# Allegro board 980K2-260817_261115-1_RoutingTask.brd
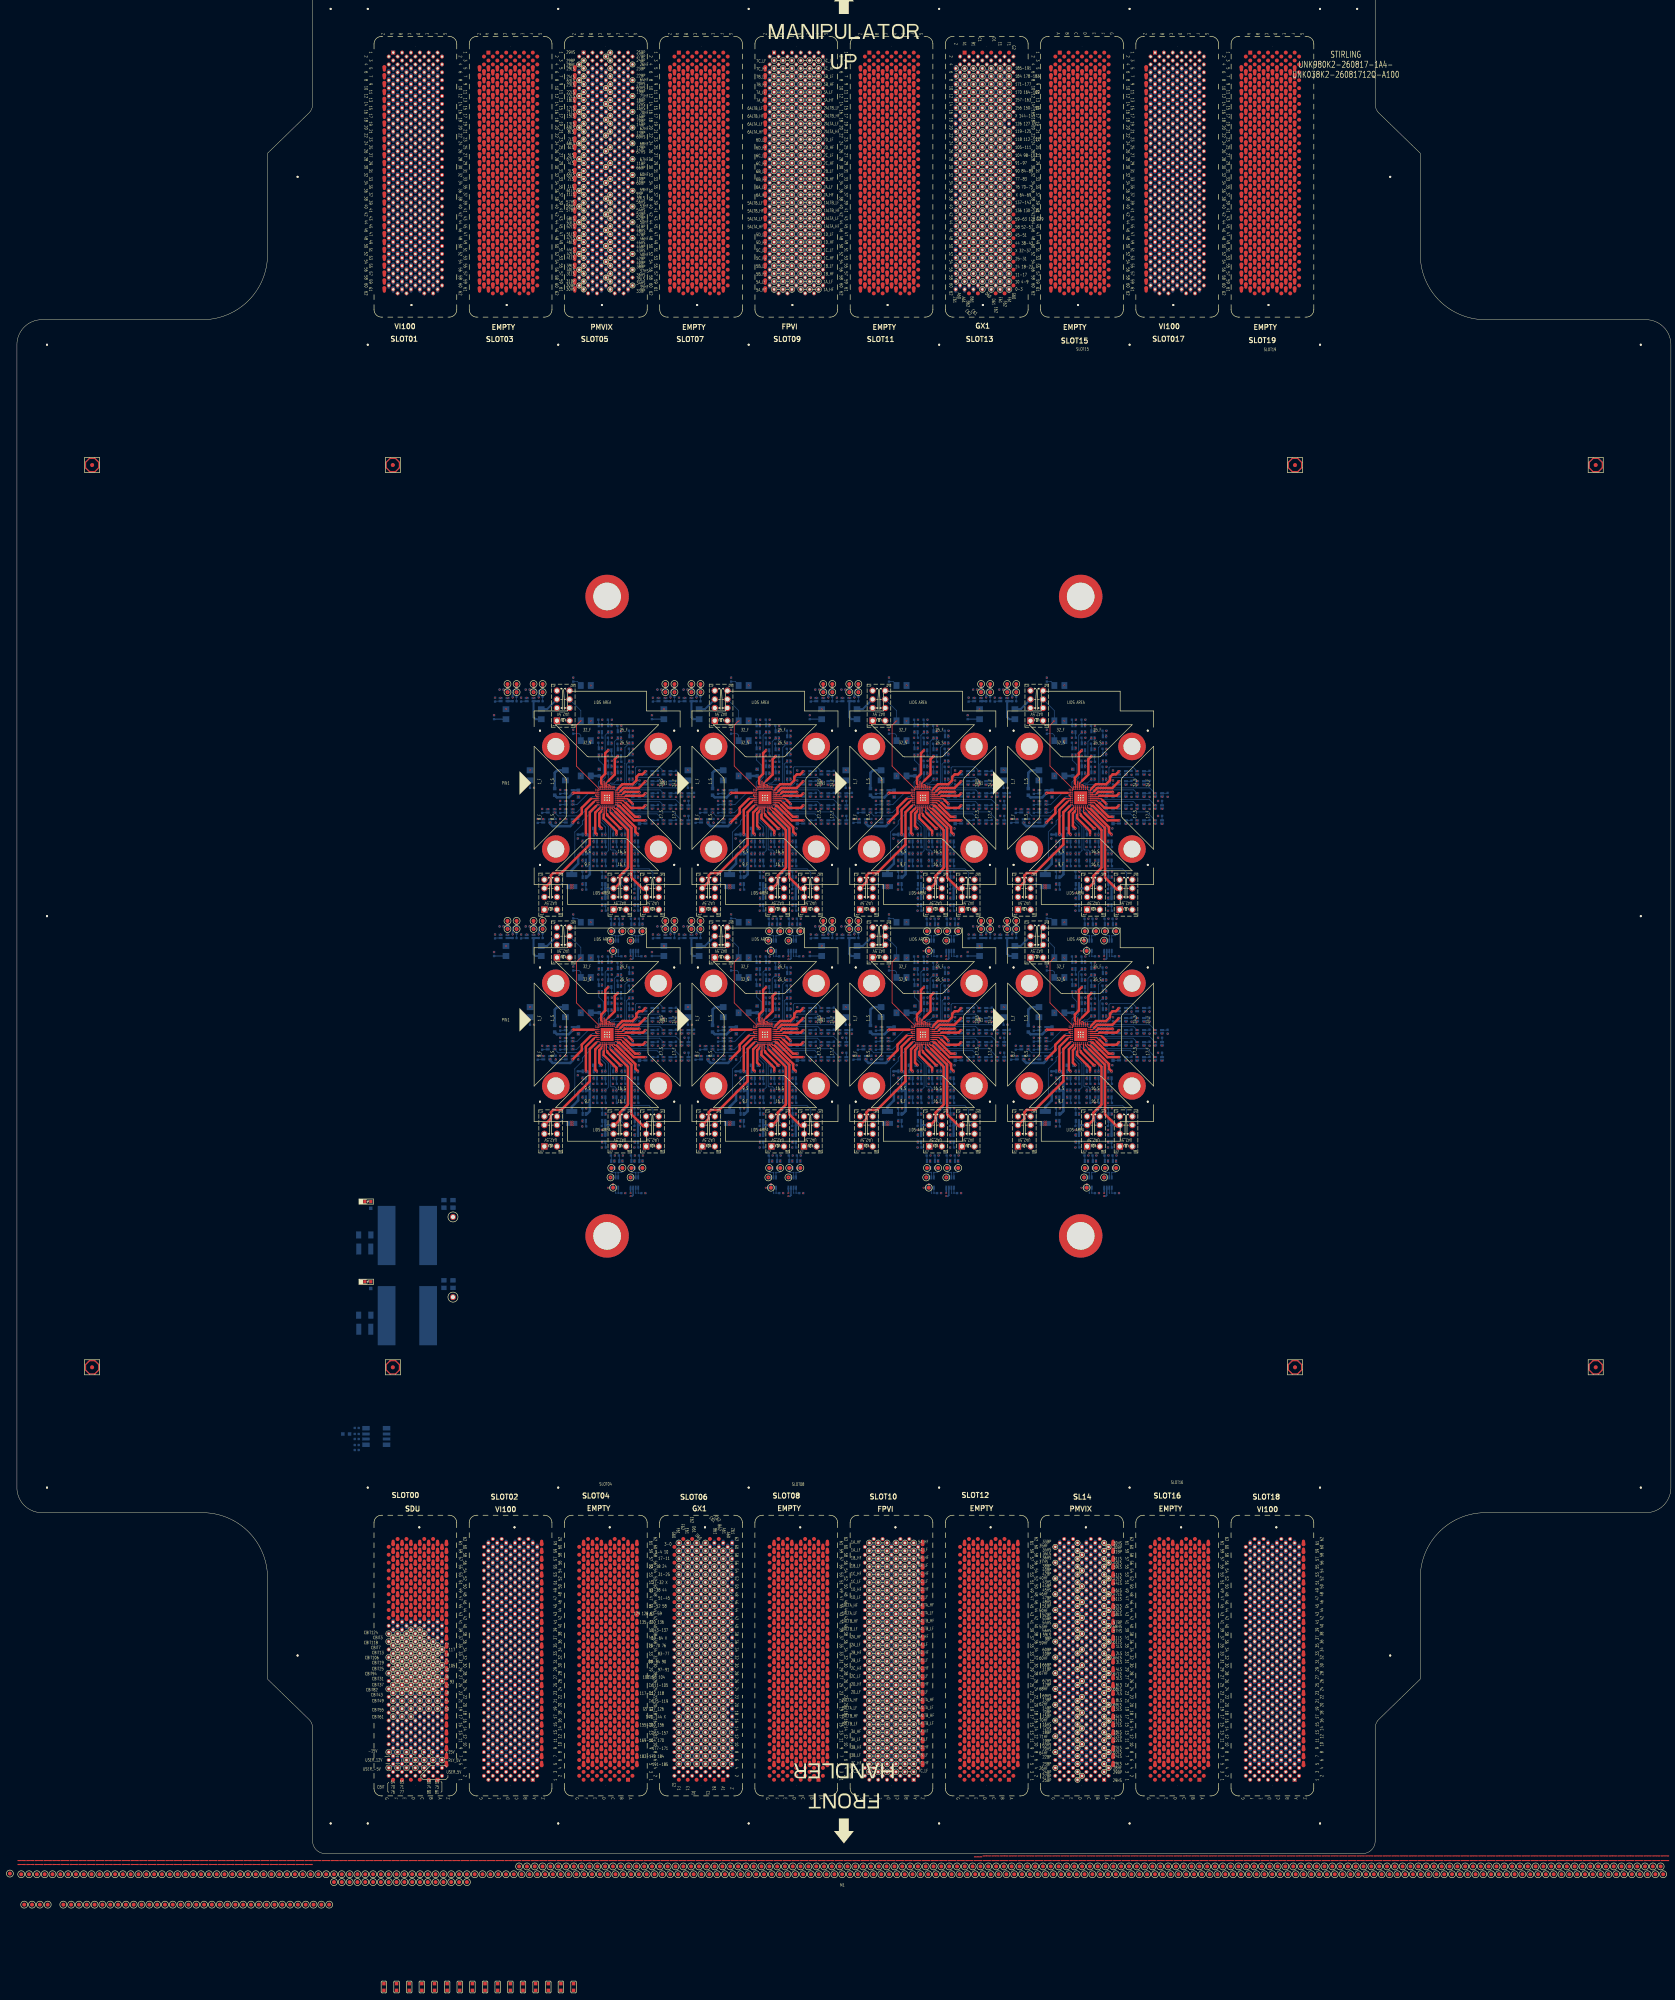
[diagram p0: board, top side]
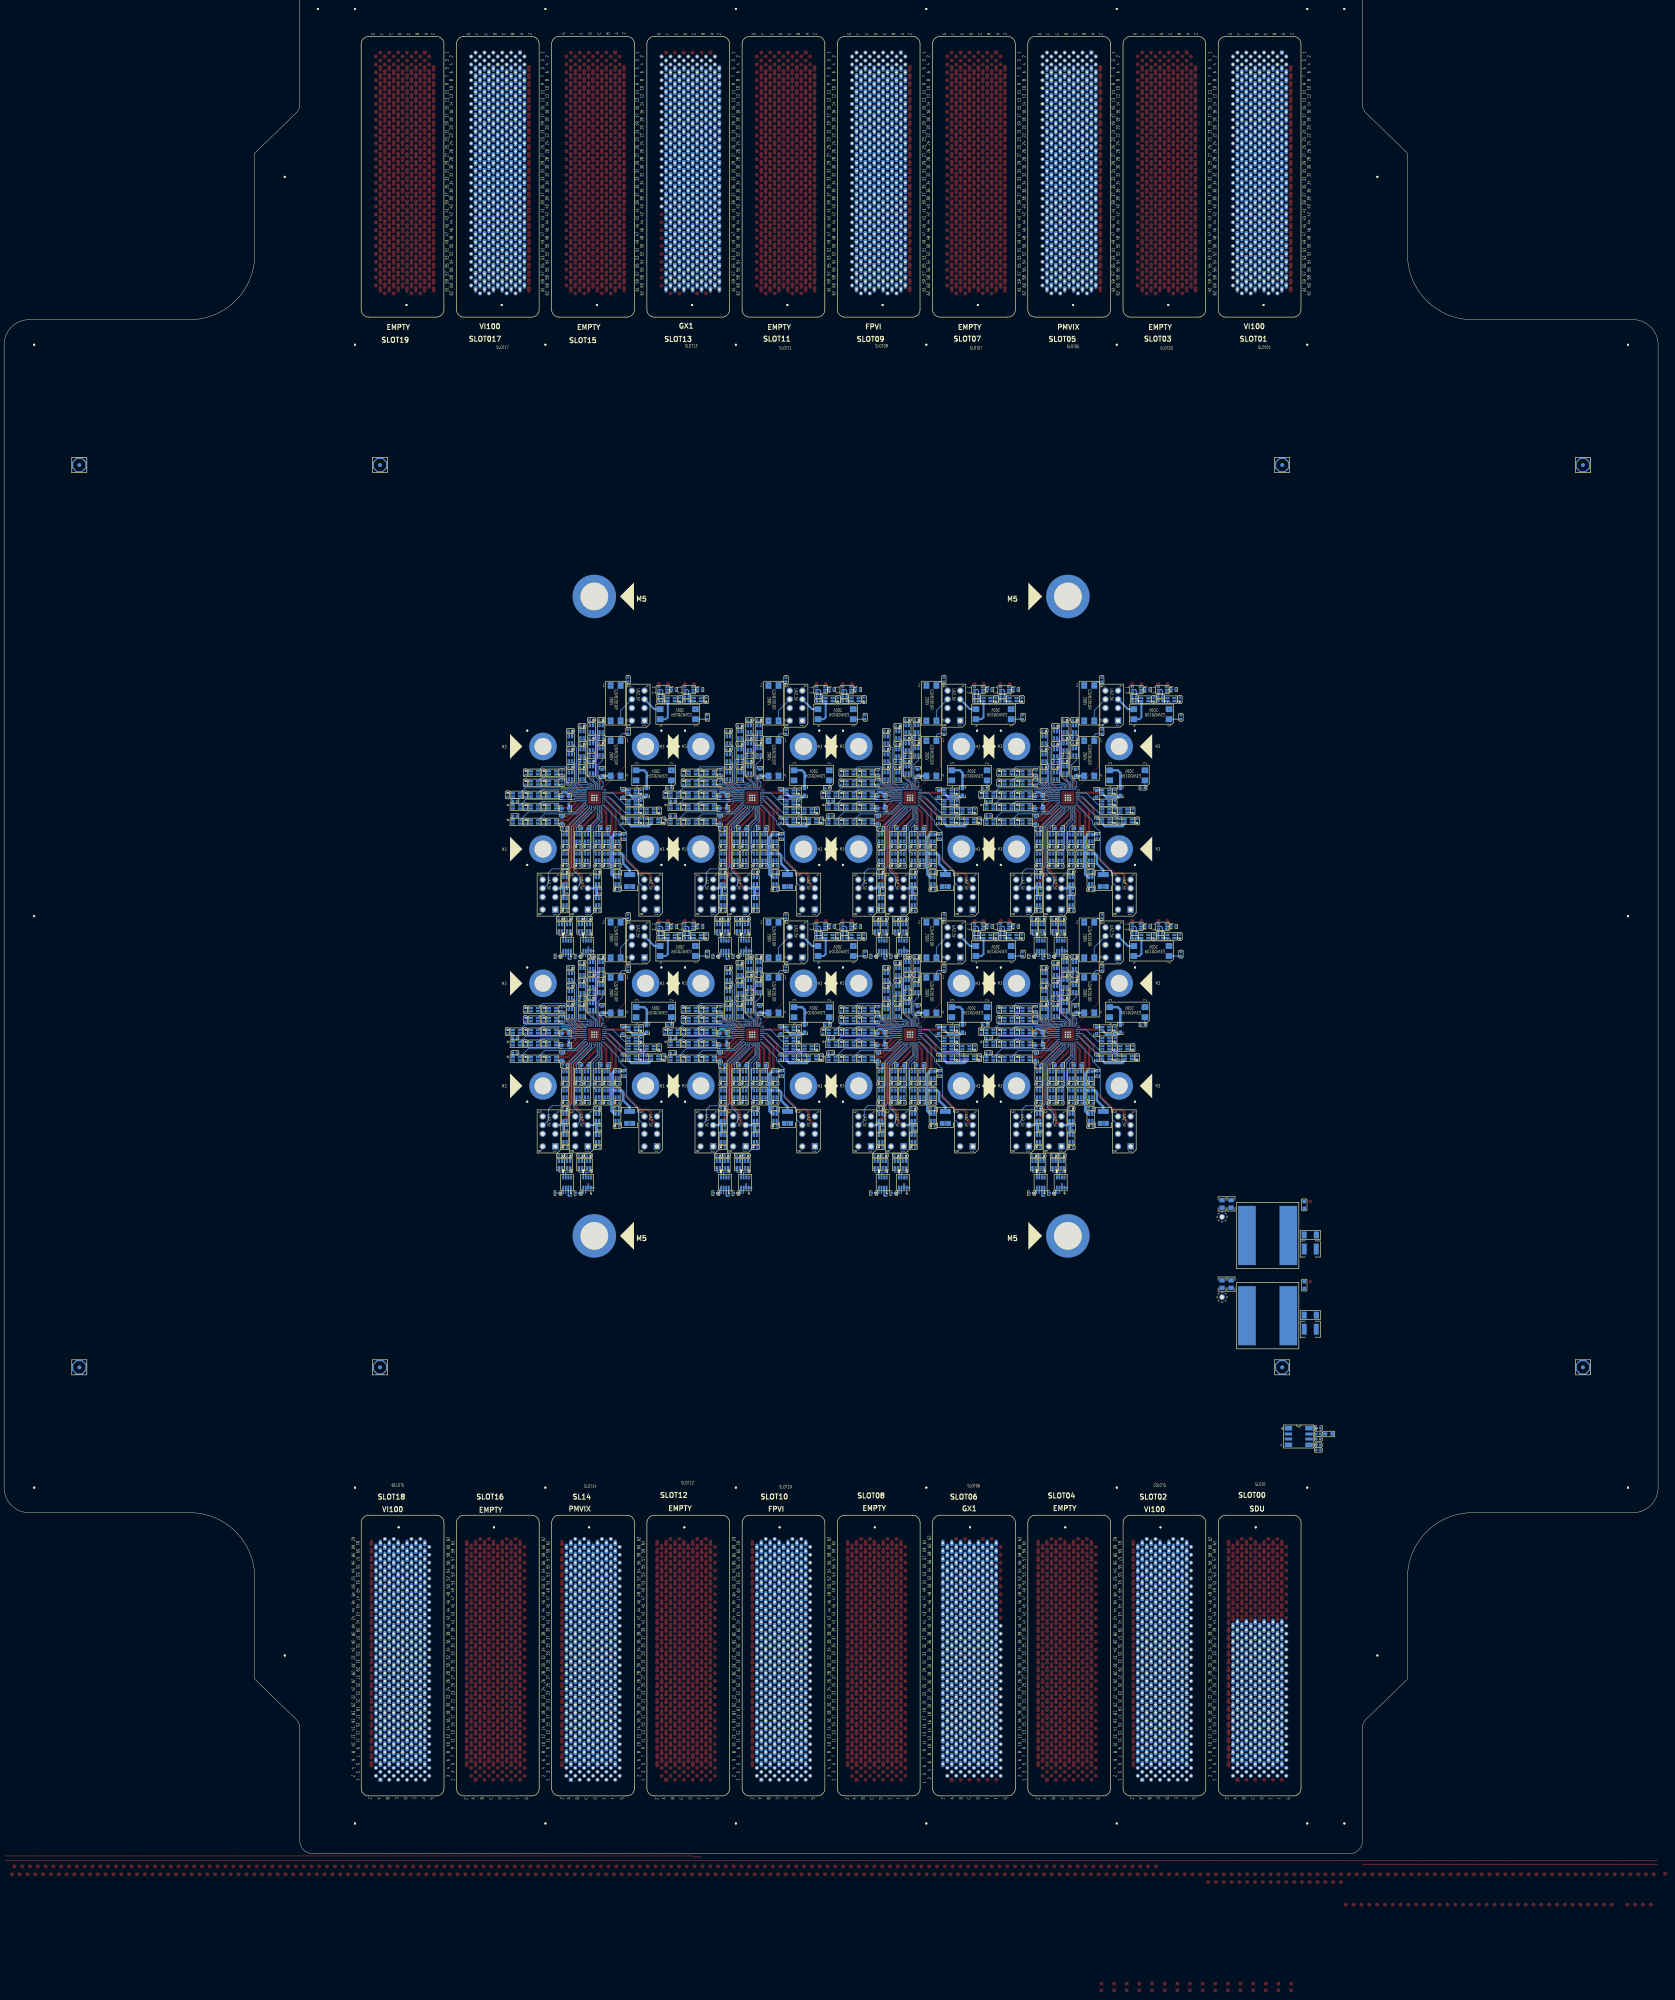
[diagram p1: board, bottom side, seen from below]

Outline 419.1 x 474.98 mm; copper layers: TOP, L02_GND, L03_DP, L04_GND, L05_DP, L06_GND, L07_VI, L08_GND, L09_VI, L10_GND, L11_VI, L12_GND, L13_VI, L14_GND, L15_5V, L16_5V, L17_C-BIT, L18_C-BIT, L19_GND, L20_VI, L21_GND, L22_VI, L23_GND, L24_VI, L25_GND, L26_VI, L27_GND, L28_DP, L29_GND, L30_DP, L31_GND, BOTTOM. Coordinates in mm from the lower left corner of the outline.

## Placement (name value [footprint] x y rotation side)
BC9  0.1U-50-X-S4-TDK  [C0402]  86.11 107.82 180 bottom
BR5  1K-1-S4  [R0402]  86.11 106.3 0 bottom
BR6  1K-1-S4  [R0402]  86.11 103.5 0 bottom
BR7  0-5-S6  [R0603]  83.44 106.3 180 bottom
BR8  0-5-S4  [R0402]  86.11 105.03 180 bottom
BR9  0-5-S4  [R0402]  86.11 102.24 180 bottom
BU1  AT24C512C-SSHM-T-SOIC8  [SO8_206X127MM]  91.06 105.66 180 bottom
C48  0.01U-100-X7R-S6-MU  [C0603]  147.57 273.87 90 bottom
C49  0.01U-100-X7R-S6-MU  [C0603]  136.27 268.99 270 bottom
C50  0.01U-100-X7R-S6-MU  [C0603]  142.28 268.54 270 bottom
C53  1U-16-X5R-S4-YA  [C0402]  142.24 261.62 270 bottom
C54  2.2U-16-X-S4-MU  [C0402]  136.53 261.62 270 bottom
C58  1U-16-X5R-S4-YA  [C0402]  142.11 257.68 270 bottom
C59  4.7U-100-X-SB-MU  [C1210]  140.59 246.51 270 bottom
C60  0.01U-100-X7R-S6-MU  [C0603]  147.01 259.72 0 bottom
C61  0.01U-100-X7R-S6-MU  [C0603]  156.88 264.78 180 bottom
C62  2.2U-16-X-S4-MU  [C0402]  157.07 259.72 0 bottom
C63  0.01U-100-X7R-S6-MU  [C0603]  157.73 261.82 90 bottom
C64  0.01U-100-X7R-S6-MU  [C0603]  156.88 267.82 180 bottom
C65  0.1U-25-X7R-S4-MU  [C0402]  157.73 271.37 90 bottom
C66  0.1U-25-X7R-S4-MU  [C0402]  152.65 276.61 180 bottom
C67  0.1U-25-X7R-S4-MU  [C0402]  150.24 278.13 180 bottom
C68  0.1U-25-X7R-S4-MU  [C0402]  147.83 282.7 180 bottom
C69  0.01U-100-X7R-S6-MU  [C0603]  151.96 259.72 0 bottom
C70  0.1U-25-X7R-S4-MU  [C0402]  122.8 294.89 180 bottom
C71  0.1U-25-X7R-S4-MU  [C0402]  129.42 294.89 180 bottom
C72  0.1U-25-X7R-S4-MU  [C0402]  158.75 227.33 0 bottom
C73  0.1U-25-X7R-S4-MU  [C0402]  153.67 227.33 0 bottom
C74  0.1U-25-X7R-S4-MU  [C0402]  157.73 273.91 90 bottom
CT1  47U-16-X5R-SB-MU  [C1210]  88.14 153.16 180 bottom
CT2  10U-16-X5R-S8-TY  [C0805]  108.2 164.59 90 bottom
CT3  22U-16-X-S8-MU  [C0805]  110.49 164.59 90 bottom
CT7  47U-16-X5R-SB-MU  [C1210]  88.14 132.84 180 bottom
CT8  10U-16-X5R-S8-TY  [C0805]  110.49 144.27 90 bottom
CT9  22U-16-X-S8-MU  [C0805]  108.2 144.27 90 bottom
F1  C1F8-0.25A-SA  [FUSE_1206_H1P05MM]  88.14 156.72 0 bottom
F2  C1F8-0.25A-SA  [FUSE_1206_H1P05MM]  88.14 136.4 0 bottom
FD1  -  [FD_040_V2]  95.25 123.19 0 top
FD2  -  [FD_040_V2]  323.85 123.19 0 top
FD3  -  [FD_040_V2]  323.85 351.79 0 top
FD4  -  [FD_040_V2]  95.25 351.79 0 top
FD5  -  [FD_040_V2]  323.85 123.19 180 bottom
FD6  -  [FD_040_V2]  95.25 123.19 180 bottom
FD7  -  [FD_040_V2]  95.25 351.79 180 bottom
FD8  -  [FD_040_V2]  323.85 351.79 180 bottom
FD9  -  [FD_040_V2]  19.05 123.19 0 top
FD10  -  [FD_040_V2]  400.05 123.19 0 top
FD11  -  [FD_040_V2]  400.05 351.79 0 top
FD12  -  [FD_040_V2]  19.05 351.79 0 top
FD13  -  [FD_040_V2]  400.05 123.19 180 bottom
FD14  -  [FD_040_V2]  19.05 123.19 180 bottom
FD15  -  [FD_040_V2]  19.05 351.79 180 bottom
FD16  -  [FD_040_V2]  400.05 351.79 180 bottom
K1  UA2-5NJ-A-V3  [RL_NECUA2_5V_V3]  138.43 290.63 270 bottom
K2  G3VM-201DR  [RL_G3VM201DR_200V]  144.15 277.5 0 bottom
K3  G3VM-201DR  [RL_G3VM201DR_200V]  134.49 273.18 90 bottom
K4  G3VM-201DR  [RL_G3VM201DR_200V]  144.15 291.47 0 bottom
K5  G3VM-51UR-5V-VSON4  [RL_G3VM_4P_VSON4]  139.95 268.99 0 bottom
K6  G3VM-51UR-5V-VSON4  [RL_G3VM_4P_VSON4]  139.95 266.19 0 bottom
K7  G3VM-51UR-5V-VSON4  [RL_G3VM_4P_VSON4]  139.95 264.16 0 bottom
K8  G3VM-51UR-5V-VSON4  [RL_G3VM_4P_VSON4]  139.95 261.62 0 bottom
K9  G3VM-51UR-5V-VSON4  [RL_G3VM_4P_VSON4]  134.24 261.62 0 bottom
K10  G3VM-51UR-5V-VSON4  [RL_G3VM_4P_VSON4]  135.38 264.16 0 bottom
K11  G3VM-51UR-5V-VSON4  [RL_G3VM_4P_VSON4]  143.76 257.3 90 bottom
K12  G3VM-51UR-5V-VSON4  [RL_G3VM_4P_VSON4]  143.76 252.48 90 bottom
K13  G3VM-51UR-5V-VSON4  [RL_G3VM_4P_VSON4]  143.76 246.51 90 bottom
K14  G3VM-51UR-5V-VSON4  [RL_G3VM_4P_VSON4]  146.56 252.48 90 bottom
K15  UA2-5NJ-A-V3  [RL_NECUA2_5V_V3]  135.25 242.75 270 bottom
K16  G3VM-51UR-5V-VSON4  [RL_G3VM_4P_VSON4]  146.56 257.3 90 bottom
K17  G3VM-51UR-5V-VSON4  [RL_G3VM_4P_VSON4]  148.72 257.3 90 bottom
K18  G3VM-51UR-5V-VSON4  [RL_G3VM_4P_VSON4]  148.72 252.48 90 bottom
K19  G3VM-51UR-5V-VSON4  [RL_G3VM_4P_VSON4]  151.51 257.3 90 bottom
K20  G3VM-51UR-5V-VSON4  [RL_G3VM_4P_VSON4]  151.51 252.48 90 bottom
K21  G3VM-51UR-5V-VSON4  [RL_G3VM_4P_VSON4]  153.67 257.3 90 bottom
K22  G3VM-51UR-5V-VSON4  [RL_G3VM_4P_VSON4]  153.67 252.48 90 bottom
K23  UA2-5NJ-A-V3  [RL_NECUA2_5V_V3]  152.78 242.75 270 bottom
K24  UA2-5NJ-A-V3  [RL_NECUA2_5V_V3]  161.04 242.75 270 bottom
K25  G3VM-51UR-5V-VSON4  [RL_G3VM_4P_VSON4]  156.97 257.3 90 bottom
K26  G3VM-51UR-5V-VSON4  [RL_G3VM_4P_VSON4]  156.97 252.48 90 bottom
K27  G3VM-51UR-5V-VSON4  [RL_G3VM_4P_VSON4]  160.15 261.37 180 bottom
K28  G3VM-51UR-5V-VSON4  [RL_G3VM_4P_VSON4]  164.72 261.37 180 bottom
K29  G3VM-51UR-5V-VSON4  [RL_G3VM_4P_VSON4]  169.29 261.37 180 bottom
K30  G3VM-51UR-5V-VSON4  [RL_G3VM_4P_VSON4]  160.15 265.18 180 bottom
K31  G3VM-51UR-5V-VSON4  [RL_G3VM_4P_VSON4]  164.72 265.18 180 bottom
K32  G3VM-51UR-5V-VSON4  [RL_G3VM_4P_VSON4]  169.29 265.18 180 bottom
K33  G3VM-51UR-5V-VSON4  [RL_G3VM_4P_VSON4]  160.15 268.22 180 bottom
K34  G3VM-51UR-5V-VSON4  [RL_G3VM_4P_VSON4]  164.72 268.22 180 bottom
K35  G3VM-51UR-5V-VSON4  [RL_G3VM_4P_VSON4]  169.29 268.22 180 bottom
K36  G3VM-51UR-5V-VSON4  [RL_G3VM_4P_VSON4]  160.15 271.27 180 bottom
K37  G3VM-51UR-5V-VSON4  [RL_G3VM_4P_VSON4]  164.72 271.27 180 bottom
K38  G3VM-51UR-5V-VSON4  [RL_G3VM_4P_VSON4]  160.15 273.81 180 bottom
K39  G3VM-51UR-5V-VSON4  [RL_G3VM_4P_VSON4]  164.72 273.81 180 bottom
K40  G3VM-51UR-5V-VSON4  [RL_G3VM_4P_VSON4]  155.58 273.05 270 bottom
K41  G3VM-51UR-5V-VSON4  [RL_G3VM_4P_VSON4]  155.58 277.62 270 bottom
K42  G3VM-51UR-5V-VSON4  [RL_G3VM_4P_VSON4]  155.58 282.19 270 bottom
K43  G3VM-51UR-5V-VSON4  [RL_G3VM_4P_VSON4]  152.65 273.05 270 bottom
K44  G3VM-51UR-5V-VSON4  [RL_G3VM_4P_VSON4]  152.65 278.89 270 bottom
K45  G3VM-51UR-5V-VSON4  [RL_G3VM_4P_VSON4]  152.65 283.46 270 bottom
K46  G3VM-51UR-5V-VSON4  [RL_G3VM_4P_VSON4]  150.24 274.57 270 bottom
K47  G3VM-51UR-5V-VSON4  [RL_G3VM_4P_VSON4]  150.24 280.42 270 bottom
K48  G3VM-51UR-5V-VSON4  [RL_G3VM_4P_VSON4]  150.24 284.99 270 bottom
K49  G3VM-51UR-5V-VSON4  [RL_G3VM_4P_VSON4]  147.83 284.99 270 bottom
K50  G3VM-51UR-5V-VSON4  [RL_G3VM_4P_VSON4]  147.83 279.15 270 bottom
K51  G3VM-51UR-5V-VSON4  [RL_G3VM_4P_VSON4]  148.72 246.51 270 bottom
K52  G3VM-51UR-5V-VSON4  [RL_G3VM_4P_VSON4]  148.72 241.17 90 bottom
K53  G3VM-51UR-5V-VSON4  [RL_G3VM_4P_VSON4]  156.97 246.51 270 bottom
K54  G3VM-51UR-5V-VSON4  [RL_G3VM_4P_VSON4]  156.97 241.17 90 bottom
K55  G3VM-51UR-5V-VSON4  [RL_G3VM_4P_VSON4]  123.44 292.35 0 bottom
K56  G3VM-201DR  [RL_G3VM201DR_200V]  128.4 288.67 90 bottom
K57  G3VM-51UR-5V-VSON4  [RL_G3VM_4P_VSON4]  158.12 234.57 270 bottom
K58  G3VM-51UR-5V-VSON4  [RL_G3VM_4P_VSON4]  156.08 234.57 270 bottom
K59  G3VM-51UR-5V-VSON4  [RL_G3VM_4P_VSON4]  153.04 234.57 270 bottom
K60  G3VM-51UR-5V-VSON4  [RL_G3VM_4P_VSON4]  151 234.57 270 bottom
K61  G3VM-51UR-5V-VSON4  [RL_G3VM_4P_VSON4]  130.05 292.35 0 bottom
LD1  LDG-2-S6  [LED_0603]  88.91 165.19 0 top
LD3  LDG-2-S6  [LED_0603]  88.91 144.87 0 top
LT1  L10U-16A-S16.5X15.5-PU  [IND_16P5X15P5MM]  98.93 156.59 0 bottom
LT3  L10U-16A-S16.5X15.5-PU  [IND_16P5X15P5MM]  98.93 136.27 0 bottom
M1  PG_LTXDX_F_X1_OUTLINE_TD_V2  [PG_LTXDX_F_X1_OUTLINE_TD_COHU]  209.55 237.49 0 top
NOREF  -  []  175.11 261.22 90 top
NOREF#2  -  []  255.11 201.22 90 top
NOREF#3  -  []  269.84 224.11 90 top
NOREF#4  -  []  276.61 233.37 90 top
NOREF#5  -  []  138.35 207.01 0 top
NOREF#6  -  []  141.03 207.69 90 top
NOREF#7  -  []  169.52 200.42 90 top
NOREF#8  -  []  271.24 197.85 90 top
NOREF#9  -  []  214.09 204.23 90 top
NOREF#10  -  []  270.6 173.69 90 top
NOREF#11  -  []  274.39 276.17 90 top
NOREF#12  -  []  230.56 252.78 0 top
NOREF#13  -  []  269.12 196.43 90 top
NOREF#14  -  []  132.26 248.4 0 top
NOREF#15  -  []  193.39 197.85 90 top
NOREF#16  -  []  283.84 270.87 90 top
NOREF#17  -  []  181.55 209.94 90 top
NOREF#18  -  []  205.38 286.23 0 top
NOREF#19  -  []  212.55 224.49 0 top
NOREF#20  -  []  169.52 260.42 90 top
NOREF#21  -  []  197.37 251.6 90 top
NOREF#22  -  []  283.84 274.21 0 top
NOREF#23  -  []  161.75 214.76 0 top
NOREF#24  -  []  153.18 184.35 0 top
NOREF#25  -  []  226.16 200.17 90 top
NOREF#26  -  []  274.33 264.33 90 top
NOREF#27  -  []  249.52 267.27 90 top
NOREF#28  -  []  151.7 285.06 90 top
NOREF#29  -  []  214.09 264.23 90 top
NOREF#30  -  []  199.27 213.41 90 top
NOREF#31  -  []  154.07 191.6 90 top
NOREF#32  -  []  239.4 202.09 0 top
NOREF#33  -  []  230.77 279.22 90 top
NOREF#34  -  []  262.81 252.78 0 top
NOREF#35  -  []  143.49 187.06 90 top
NOREF#36  -  []  192.87 188.11 90 top
NOREF#37  -  []  276.52 221.12 0 top
NOREF#38  -  []  140.59 244.98 90 top
NOREF#39  -  []  155.92 190.88 90 top
NOREF#40  -  []  228.95 266.89 0 top
NOREF#41  -  []  281.12 188.11 90 top
NOREF#42  -  []  162.57 231.95 0 top
NOREF#43  -  []  171.25 184.35 0 top
NOREF#44  -  []  186.16 193.35 0 top
NOREF#45  -  []  163.84 211.67 0 top
NOREF#46  -  []  144.04 251.93 0 top
NOREF#47  -  []  236.57 198.18 0 top
NOREF#48  -  []  163.84 214.21 0 top
NOREF#49  -  []  179.55 240.49 90 top
NOREF#50  -  []  233.83 232.21 90 top
NOREF#51  -  []  182.81 257.6 0 top
NOREF#52  -  []  132.55 224.49 0 top
NOREF#53  -  []  275.15 176.17 90 top
NOREF#54  -  []  141.85 232.5 0 top
NOREF#55  -  []  195.17 276.75 0 top
NOREF#56  -  []  244.44 292.28 90 top
NOREF#57  -  []  172.87 287.4 90 top
NOREF#58  -  []  204.95 210.32 90 top
NOREF#59  -  []  228.78 244.35 0 top
NOREF#60  -  []  268.89 392.33 90 top
NOREF#61  -  []  228.32 182.05 0 top
NOREF#62  -  []  183.89 185.24 90 top
NOREF#63  -  []  163.92 229.94 0 top
NOREF#64  -  []  262.87 226.99 0 top
NOREF#65  -  []  152.46 247.68 90 top
NOREF#66  -  []  189.67 190.01 0 top
NOREF#67  -  []  279.27 210.87 90 top
NOREF#68  -  []  228.19 247.71 0 top
NOREF#69  -  []  275.17 272.17 0 top
NOREF#70  -  []  286.32 269.17 0 top
NOREF#71  -  []  267.8 205.39 90 top
NOREF#72  -  []  132.87 227.4 90 top
NOREF#73  -  []  187.43 218.27 90 top
NOREF#74  -  []  141.83 265.99 0 top
NOREF#75  -  []  231.98 220.75 90 top
NOREF#76  -  []  145.42 226.99 90 top
NOREF#77  -  []  149.29 289.79 0 top
NOREF#78  -  []  191.91 251.6 90 top
NOREF#79  -  []  221.85 306.46 0 top
NOREF#80  -  []  283.84 211.67 0 top
NOREF#81  -  []  196.61 233.37 90 top
NOREF#82  -  []  269.84 213.7 90 top
NOREF#83  -  []  191.19 228.49 0 top
NOREF#84  -  []  159.4 265.9 0 top
NOREF#85  -  []  264.16 251.6 90 top
NOREF#86  -  []  195.49 228.7 90 top
NOREF#87  -  []  85.59 135.25 90 top
NOREF#88  -  []  175.02 268.14 90 top
NOREF#89  -  []  253.64 239.09 0 top
NOREF#90  -  []  259.08 265.79 0 top
NOREF#91  -  []  153.98 238.07 0 top
NOREF#92  -  []  252.55 224.49 0 top
NOREF#93  -  []  155.05 214.25 0 top
NOREF#94  -  []  168.54 205.9 0 top
NOREF#95  -  []  131.05 185.49 90 top
NOREF#96  -  []  229.12 256.43 90 top
NOREF#97  -  []  155.17 212.18 0 top
NOREF#98  -  []  276.33 167.9 90 top
NOREF#99  -  []  174.51 203.76 0 top
NOREF#100  -  []  276.1 271.85 90 top
NOREF#101  -  []  155.68 233.69 90 top
NOREF#102  -  []  189.12 240.3 90 top
NOREF#103  -  []  178.35 204.47 0 top
NOREF#104  -  []  206.32 206.13 0 top
NOREF#105  -  []  232.63 172.86 0 top
NOREF#106  -  []  280.23 236.17 90 top
NOREF#107  -  []  185.09 197.49 90 top
NOREF#108  -  []  161.44 184.35 0 top
NOREF#109  -  []  228.35 223.79 90 top
NOREF#110  -  []  170.89 269.17 0 top
NOREF#111  -  []  163.84 267.82 90 top
NOREF#112  -  []  161.84 235.2 0 top
NOREF#113  -  []  170.89 266.13 0 top
NOREF#114  -  []  149.29 286.59 90 top
NOREF#115  -  []  179.08 265.79 0 top
NOREF#116  -  []  268.44 193.03 90 top
NOREF#117  -  []  242.2 238.35 0 top
NOREF#118  -  []  260.83 261.22 90 top
NOREF#119  -  []  195.17 221.32 90 top
NOREF#120  -  []  279.65 212.56 0 top
NOREF#121  -  []  129.17 291.95 0 top
NOREF#122  -  []  125.38 226.23 0 top
NOREF#123  -  []  250.02 214.45 0 top
NOREF#124  -  []  209.49 280.89 0 top
NOREF#125  -  []  239.72 219.22 90 top
NOREF#126  -  []  188.78 244.35 0 top
NOREF#127  -  []  176.63 232.23 0 top
NOREF#128  -  []  155.17 272.17 0 top
NOREF#129  -  []  284.64 241.15 90 top
NOREF#130  -  []  137.28 272.5 90 top
NOREF#131  -  []  146.16 193.35 0 top
NOREF#132  -  []  226.83 256.75 0 top
NOREF#133  -  []  152.13 220.09 0 top
NOREF#134  -  []  239.4 273.09 90 top
NOREF#135  -  []  290.89 269.17 0 top
NOREF#136  -  []  181.6 248.12 0 top
NOREF#137  -  []  283.84 214.21 0 top
NOREF#138  -  []  208.54 260.64 90 top
NOREF#139  -  []  148.24 392.33 90 top
NOREF#140  -  []  288.54 268.95 0 top
NOREF#141  -  []  243.97 208.95 0 top
NOREF#142  -  []  277.71 233.69 0 top
NOREF#143  -  []  171.22 294.24 90 top
NOREF#144  -  []  208.42 261.77 0 top
NOREF#145  -  []  189.24 245.31 90 top
NOREF#146  -  []  235.49 228.7 90 top
NOREF#147  -  []  203.84 200.97 90 top
NOREF#148  -  []  228.99 180.62 0 top
NOREF#149  -  []  159.4 208.95 0 top
NOREF#150  -  []  231.19 223.92 0 top
NOREF#151  -  []  234.33 204.33 90 top
NOREF#152  -  []  244.95 270.32 90 top
NOREF#153  -  []  151.79 191.93 0 top
NOREF#154  -  []  192.72 192.78 0 top
NOREF#155  -  []  131.22 234.89 90 top
NOREF#156  -  []  152.51 175.77 0 top
NOREF#157  -  []  124.44 292.28 90 top
NOREF#158  -  []  264.16 196.43 90 top
NOREF#159  -  []  236.45 187.71 0 top
NOREF#160  -  []  267.77 197.6 0 top
NOREF#161  -  []  261.85 232.5 0 top
NOREF#162  -  []  218.95 206.12 0 top
NOREF#163  -  []  182.81 186.81 0 top
NOREF#164  -  []  286.32 206.13 0 top
NOREF#165  -  []  230.56 257.6 0 top
NOREF#166  -  []  199.27 270.87 90 top
NOREF#167  -  []  204.95 212.86 90 top
NOREF#168  -  []  270.15 266.89 90 top
NOREF#169  -  []  205.74 14.59 90 top
NOREF#170  -  []  153.27 198.18 0 top
NOREF#171  -  []  234.07 196.43 90 top
NOREF#172  -  []  211.25 184.35 0 top
NOREF#173  -  []  231.19 278.07 0 top
NOREF#174  -  []  175.65 184.35 0 top
NOREF#175  -  []  209.49 220.89 0 top
NOREF#176  -  []  275.05 214.25 0 top
NOREF#177  -  []  231.18 239.15 0 top
NOREF#178  -  []  149.84 219.54 90 top
NOREF#179  -  []  223.49 253.03 90 top
NOREF#180  -  []  226.16 212.17 90 top
NOREF#181  -  []  222.81 192.78 0 top
NOREF#182  -  []  233.18 222.26 90 top
NOREF#183  -  []  151.19 218.07 0 top
NOREF#184  -  []  290.89 209.17 0 top
NOREF#185  -  []  274.07 191.6 90 top
NOREF#186  -  []  215.02 208.14 90 top
NOREF#187  -  []  246.32 274.76 0 top
NOREF#188  -  []  199.72 279.22 90 top
NOREF#189  -  []  187.05 209.24 0 top
NOREF#190  -  []  211.14 458.49 0 top
NOREF#191  -  []  95.33 18.69 0 top
NOREF#192  -  []  196.52 276.55 0 top
NOREF#193  -  []  149.84 279.54 90 top
NOREF#194  -  []  232.25 212.18 0 top
NOREF#195  -  []  241.44 184.35 0 top
NOREF#196  -  []  156.02 247.68 0 top
NOREF#197  -  []  138.95 201.55 0 top
NOREF#198  -  []  228.99 191.93 0 top
NOREF#199  -  []  142.88 213.02 0 top
NOREF#200  -  []  163.97 264.45 90 top
NOREF#201  -  []  213.24 201.55 0 top
NOREF#202  -  []  143.49 193.03 90 top
NOREF#203  -  []  204.61 234.89 90 top
NOREF#204  -  []  276.7 241.72 90 top
NOREF#205  -  []  267.3 280.35 0 top
NOREF#206  -  []  154.62 247.68 90 top
NOREF#207  -  []  188.32 185.63 0 top
NOREF#208  -  []  191.87 456.29 0 top
NOREF#209  -  []  149.55 318.49 0 top
NOREF#210  -  []  159.27 211.67 0 top
NOREF#211  -  []  265.41 213.02 90 top
NOREF#212  -  []  176.72 18.69 0 top
NOREF#213  -  []  217.29 187.78 0 top
NOREF#214  -  []  225.61 252.78 0 top
NOREF#215  -  []  200.23 176.17 90 top
NOREF#216  -  []  276.52 281.12 0 top
NOREF#217  -  []  133.62 289.09 90 top
NOREF#218  -  []  228.99 240.62 0 top
NOREF#219  -  []  153.39 253.03 90 top
NOREF#220  -  []  261.55 207.14 90 top
NOREF#221  -  []  220.95 201.55 90 top
NOREF#222  -  []  185.41 226.99 90 top
NOREF#223  -  []  142.81 186.81 0 top
NOREF#224  -  []  131.26 244.35 0 top
NOREF#225  -  []  226.16 198.18 0 top
NOREF#226  -  []  138.95 204.09 0 top
NOREF#227  -  []  216.26 203.76 90 top
NOREF#228  -  []  261.03 207.69 90 top
NOREF#229  -  []  236.54 167 0 top
NOREF#230  -  []  192.63 233.69 0 top
NOREF#231  -  []  156.57 258.18 0 top
NOREF#232  -  []  145.42 213.02 90 top
NOREF#233  -  []  279.4 200.64 90 top
NOREF#234  -  []  269.84 219.54 0 top
NOREF#235  -  []  157.92 236.37 90 top
NOREF#236  -  []  89.74 155.92 90 top
NOREF#237  -  []  261.59 294.14 0 top
NOREF#238  -  []  153.18 277.69 90 top
NOREF#239  -  []  147.8 205.39 90 top
NOREF#240  -  []  265.61 252.78 0 top
NOREF#241  -  []  180.83 268.59 90 top
NOREF#242  -  []  279.4 208.95 0 top
NOREF#243  -  []  199.27 201.77 0 top
NOREF#244  -  []  261.03 267.69 90 top
NOREF#245  -  []  236.8 280.49 90 top
NOREF#246  -  []  163.97 202.09 0 top
NOREF#247  -  []  167.98 286.38 90 top
NOREF#248  -  []  239.4 272 0 top
NOREF#249  -  []  151.11 193.35 0 top
NOREF#250  -  []  191.24 197.85 90 top
NOREF#251  -  []  283.97 205.9 0 top
NOREF#252  -  []  184.16 185.63 90 top
NOREF#253  -  []  216.83 287.03 0 top
NOREF#254  -  []  195.17 281.32 90 top
NOREF#255  -  []  149.72 275.77 0 top
NOREF#256  -  []  154.63 274.65 90 top
NOREF#257  -  []  248.54 204.45 90 top
NOREF#258  -  []  256.83 227.03 0 top
NOREF#259  -  []  156.52 225.69 0 top
NOREF#260  -  []  124.61 234.24 90 top
NOREF#261  -  []  271.91 196.43 90 top
NOREF#262  -  []  215.65 184.35 0 top
NOREF#263  -  []  139.08 263.76 0 top
NOREF#264  -  []  188.99 240.62 0 top
NOREF#265  -  []  235.05 214.25 0 top
NOREF#266  -  []  127.04 239.09 0 top
NOREF#267  -  []  196.57 245.63 90 top
NOREF#268  -  []  154.39 216.17 90 top
NOREF#269  -  []  149.55 156.49 90 top
NOREF#270  -  []  147.77 248.11 90 top
NOREF#271  -  []  202.85 297.22 0 top
NOREF#272  -  []  230.97 195.7 90 top
NOREF#273  -  []  256.83 287.03 0 top
NOREF#274  -  []  152.66 226.35 90 top
NOREF#275  -  []  133.78 207.01 0 top
NOREF#276  -  []  156.7 257.85 90 top
NOREF#277  -  []  195.17 221.32 0 top
NOREF#278  -  []  191.91 191.6 90 top
NOREF#279  -  []  248.54 262.09 0 top
NOREF#280  -  []  191.19 288.49 0 top
NOREF#281  -  []  192.13 220.09 0 top
NOREF#282  -  []  208.42 200.97 90 top
NOREF#283  -  []  216.26 263.76 90 top
NOREF#284  -  []  283.53 457.2 0 top
NOREF#285  -  []  256.55 220.49 0 top
NOREF#286  -  []  288.42 200.97 90 top
NOREF#287  -  []  288.54 202.09 0 top
NOREF#288  -  []  250.89 202.32 0 top
NOREF#289  -  []  148.99 196.75 0 top
NOREF#290  -  []  270.77 223.79 90 top
NOREF#291  -  []  186.28 193.03 90 top
NOREF#292  -  []  236.79 171.3 0 top
NOREF#293  -  []  168.42 268.62 0 top
NOREF#294  -  []  180.95 266.12 90 top
NOREF#295  -  []  226.43 236.47 90 top
NOREF#296  -  []  148.95 266.89 0 top
NOREF#297  -  []  233.27 258.18 0 top
NOREF#298  -  []  266.43 222.5 90 top
NOREF#299  -  []  136.5 285.91 90 top
NOREF#300  -  []  148.99 180.62 0 top
NOREF#301  -  []  186.01 184.91 90 top
NOREF#302  -  []  204.64 241.15 90 top
NOREF#303  -  []  277.71 233.69 90 top
NOREF#304  -  []  163.97 260.64 90 top
NOREF#305  -  []  228.44 253.03 90 top
NOREF#306  -  []  214.43 232.23 0 top
NOREF#307  -  []  159.27 264.78 90 top
NOREF#308  -  []  229.84 224.11 0 top
NOREF#309  -  []  135.11 201.22 90 top
NOREF#310  -  []  237.18 236.17 90 top
NOREF#311  -  []  213.24 261.55 0 top
NOREF#312  -  []  132.55 250.49 90 top
NOREF#313  -  []  138.97 271.91 90 top
NOREF#314  -  []  191.98 286.59 90 top
NOREF#315  -  []  192.63 173.69 0 top
NOREF#316  -  []  236.1 271.85 90 top
NOREF#317  -  []  136.98 205.11 90 top
NOREF#318  -  []  267.8 204.99 90 top
NOREF#319  -  []  174.43 292.23 0 top
NOREF#320  -  []  245.73 17.15 90 top
NOREF#321  -  []  159.4 212 0 top
NOREF#322  -  []  155.17 276.75 0 top
NOREF#323  -  []  145.09 197.49 90 top
NOREF#324  -  []  281.75 272.22 0 top
NOREF#325  -  []  149.29 282.02 90 top
NOREF#326  -  []  133.4 281.8 90 top
NOREF#327  -  []  196.52 216.55 0 top
NOREF#328  -  []  218.35 204.47 0 top
NOREF#329  -  []  152.63 173.69 90 top
NOREF#330  -  []  203.84 265.58 0 top
NOREF#331  -  []  258.95 261.55 0 top
NOREF#332  -  []  197.25 240.62 0 top
NOREF#333  -  []  232.72 192.78 0 top
NOREF#334  -  []  184.04 196.75 0 top
NOREF#335  -  []  140.95 264.09 90 top
NOREF#336  -  []  227.3 286.19 0 top
NOREF#337  -  []  189.55 248.99 90 top
NOREF#338  -  []  199.27 271.67 0 top
NOREF#339  -  []  173.62 229.09 90 top
NOREF#340  -  []  269.86 17.15 90 top
NOREF#341  -  []  140.95 261.55 90 top
NOREF#342  -  []  159.4 270.55 90 top
NOREF#343  -  []  260.83 203.76 90 top
NOREF#344  -  []  185.61 192.78 0 top
NOREF#345  -  []  259.73 178.35 0 top
NOREF#346  -  []  256.98 205.11 90 top
NOREF#347  -  []  147.03 171.4 0 top
NOREF#348  -  []  321.5 18.69 0 top
NOREF#349  -  []  226.16 193.35 0 top
NOREF#350  -  []  275.58 262.67 90 top
NOREF#351  -  []  188.44 257.85 90 top
NOREF#352  -  []  131.22 294.24 90 top
NOREF#353  -  []  272.63 232.86 0 top
NOREF#354  -  []  281.75 274.76 0 top
NOREF#355  -  []  214.09 267.27 90 top
NOREF#356  -  []  195.68 233.69 90 top
NOREF#357  -  []  180.83 208.59 90 top
NOREF#358  -  []  276.7 253.03 90 top
NOREF#359  -  []  186.16 260.17 90 top
NOREF#360  -  []  272.51 175.77 0 top
NOREF#361  -  []  180.43 224.38 90 top
NOREF#362  -  []  236.57 258.18 0 top
NOREF#363  -  []  226.96 191.6 90 top
NOREF#364  -  []  178.35 209.04 0 top
NOREF#365  -  []  150.48 235.77 0 top
NOREF#366  -  []  253.65 239.15 0 top
NOREF#367  -  []  261.55 205.11 90 top
NOREF#368  -  []  233.76 190.88 90 top
NOREF#369  -  []  255.24 261.55 90 top
NOREF#370  -  []  171.05 289.49 0 top
NOREF#371  -  []  153.03 232.1 0 top
NOREF#372  -  []  151.95 238.07 0 top
NOREF#373  -  []  197.25 251.93 0 top
NOREF#374  -  []  266.69 237.02 90 top
NOREF#375  -  []  294.99 82.65 0 top
NOREF#376  -  []  155.56 175.77 0 top
NOREF#377  -  []  220.95 268.91 90 top
NOREF#378  -  []  273.56 233.37 90 top
NOREF#379  -  []  195.05 283.39 0 top
NOREF#380  -  []  232.25 272.17 0 top
NOREF#381  -  []  151.24 257.85 90 top
NOREF#382  -  []  186.83 256.75 0 top
NOREF#383  -  []  151.11 258.18 0 top
NOREF#384  -  []  266.16 286.14 90 top
NOREF#385  -  []  275.05 218.82 0 top
NOREF#386  -  []  201.44 184.35 0 top
NOREF#387  -  []  148.35 277.95 90 top
NOREF#388  -  []  158.64 173.37 90 top
NOREF#389  -  []  190.41 228.7 90 top
NOREF#390  -  []  232.51 235.77 0 top
NOREF#391  -  []  181.22 76.69 90 top
NOREF#392  -  []  196.61 173.37 90 top
NOREF#393  -  []  147.77 252.5 0 top
NOREF#394  -  []  196.52 221.12 0 top
NOREF#395  -  []  187 83.81 0 top
NOREF#396  -  []  289.52 204.23 90 top
NOREF#397  -  []  239.22 195.7 90 top
NOREF#398  -  []  192.63 173.69 90 top
NOREF#399  -  []  146.28 257.85 90 top
NOREF#400  -  []  168.42 200.97 90 top
NOREF#401  -  []  270.41 228.7 90 top
NOREF#402  -  []  191.46 227 0 top
NOREF#403  -  []  158.89 259.3 0 top
NOREF#404  -  []  199.27 273.41 90 top
NOREF#405  -  []  276.57 245.63 0 top
NOREF#406  -  []  146.01 184.91 90 top
NOREF#407  -  []  277.71 172.86 0 top
NOREF#408  -  []  257.29 187.78 0 top
NOREF#409  -  []  192.11 231.4 0 top
NOREF#410  -  []  239.27 208.62 0 top
NOREF#411  -  []  161.75 202.32 0 top
NOREF#412  -  []  209.55 237.49 0 top
NOREF#413  -  []  215.02 268.14 90 top
NOREF#414  -  []  236.52 281.12 0 top
NOREF#415  -  []  255.65 184.35 0 top
NOREF#416  -  []  143.49 197.85 90 top
NOREF#417  -  []  220.83 268.59 90 top
NOREF#418  -  []  204.61 234.24 90 top
NOREF#419  -  []  159.27 274.21 0 top
NOREF#420  -  []  262.81 192.78 0 top
NOREF#421  -  []  238.91 172.21 90 top
NOREF#422  -  []  201.75 262.32 0 top
NOREF#423  -  []  176.55 220.49 0 top
NOREF#424  -  []  235.96 228.6 90 top
NOREF#425  -  []  267.8 209.99 0 top
NOREF#426  -  []  284.95 270.32 90 top
NOREF#427  -  []  266.16 193.35 0 top
NOREF#428  -  []  195.05 274.25 0 top
NOREF#429  -  []  153.6 226.96 0 top
NOREF#430  -  []  140.83 261.22 90 top
NOREF#431  -  []  281.75 214.76 0 top
NOREF#432  -  []  262.87 213.02 0 top
NOREF#433  -  []  196.79 171.3 0 top
NOREF#434  -  []  270.97 190.88 90 top
NOREF#435  -  []  267.3 226.19 0 top
NOREF#436  -  []  147.8 269.99 0 top
NOREF#437  -  []  161.75 206.13 0 top
NOREF#438  -  []  164.61 234.24 90 top
NOREF#439  -  []  231.46 227 0 top
NOREF#440  -  []  219.72 273.6 90 top
NOREF#441  -  []  222.81 186.81 0 top
NOREF#442  -  []  269.72 281.62 0 top
NOREF#443  -  []  203.92 289.94 0 top
NOREF#444  -  []  199.4 270.55 90 top
NOREF#445  -  []  236.52 276.55 0 top
NOREF#446  -  []  219.55 240.49 90 top
NOREF#447  -  []  271.91 251.6 90 top
NOREF#448  -  []  170.89 262.32 0 top
NOREF#449  -  []  218.95 201.55 0 top
NOREF#450  -  []  164.61 294.24 90 top
NOREF#451  -  []  239.22 250.88 90 top
NOREF#452  -  []  163.84 261.77 0 top
NOREF#453  -  []  128.94 265.53 0 top
NOREF#454  -  []  196.8 285.06 90 top
NOREF#455  -  []  184.16 256.43 90 top
NOREF#456  -  []  193.6 226.96 0 top
NOREF#457  -  []  239.24 244.35 0 top
NOREF#458  -  []  129.05 232.28 0 top
NOREF#459  -  []  125.38 226.23 0 top
NOREF#460  -  []  229.12 196.43 90 top
NOREF#461  -  []  271.46 227 0 top
NOREF#462  -  []  272.25 282.59 0 top
NOREF#463  -  []  109.54 14.59 90 top
NOREF#464  -  []  172.55 250.49 90 top
NOREF#465  -  []  166.32 214.76 0 top
NOREF#466  -  []  259.73 238.35 0 top
NOREF#467  -  []  239.72 283.79 90 top
NOREF#468  -  []  234.39 282.02 90 top
NOREF#469  -  []  239.4 265.9 0 top
NOREF#470  -  []  156.81 172.54 0 top
NOREF#471  -  []  268.99 191.93 0 top
NOREF#472  -  []  289.52 267.27 90 top
NOREF#473  -  []  203.97 200.64 90 top
NOREF#474  -  []  150.77 283.79 90 top
NOREF#475  -  []  134.43 292.23 0 top
NOREF#476  -  []  288.37 18.69 0 top
NOREF#477  -  []  276.1 276.42 90 top
NOREF#478  -  []  151.7 283.69 0 top
NOREF#479  -  []  144.71 252.5 90 top
NOREF#480  -  []  140.95 266.12 90 top
NOREF#481  -  []  199.22 255.7 90 top
NOREF#482  -  []  243.97 260.64 90 top
NOREF#483  -  []  155.68 233.69 0 top
NOREF#484  -  []  135.43 276.18 0 top
NOREF#485  -  []  279.4 260.64 90 top
NOREF#486  -  []  236.52 285.69 0 top
NOREF#487  -  []  161.75 212.22 0 top
NOREF#488  -  []  124.61 234.89 90 top
NOREF#489  -  []  243.84 267.82 90 top
NOREF#490  -  []  232.66 166.36 90 top
NOREF#491  -  []  208.42 208.62 0 top
NOREF#492  -  []  288.42 205.58 0 top
NOREF#493  -  []  288.42 201.77 0 top
NOREF#494  -  []  294.09 264.23 90 top
NOREF#495  -  []  156.57 242.05 0 top
NOREF#496  -  []  226.28 197.85 90 top
NOREF#497  -  []  278.11 172.1 0 top
NOREF#498  -  []  214.38 204.09 0 top
NOREF#499  -  []  294.09 267.27 90 top
NOREF#500  -  []  58.41 375.29 0 top
NOREF#501  -  []  148.81 195.7 90 top
NOREF#502  -  []  281.75 266.13 0 top
NOREF#503  -  []  234.07 256.43 90 top
NOREF#504  -  []  236.57 245.63 90 top
NOREF#505  -  []  271.98 226.59 90 top
NOREF#506  -  []  178.85 181.15 90 top
NOREF#507  -  []  271.19 288.49 0 top
NOREF#508  -  []  230.97 239.57 90 top
NOREF#509  -  []  189.84 273.7 90 top
NOREF#510  -  []  193.27 193.35 0 top
NOREF#511  -  []  239.4 262.09 0 top
NOREF#512  -  []  276.02 181.47 0 top
NOREF#513  -  []  211.05 289.49 0 top
NOREF#514  -  []  283.84 261.77 0 top
NOREF#515  -  []  228.32 185.63 0 top
NOREF#516  -  []  155.78 237.5 90 top
NOREF#517  -  []  159.27 207.82 90 top
NOREF#518  -  []  226.16 286.14 90 top
NOREF#519  -  []  157.04 244.35 0 top
NOREF#520  -  []  249.52 270.32 90 top
NOREF#521  -  []  272.25 278.02 0 top
NOREF#522  -  []  135.15 260.67 90 top
NOREF#523  -  []  185.42 274.72 90 top
NOREF#524  -  []  268.99 256.75 0 top
NOREF#525  -  []  189.72 215.77 0 top
NOREF#526  -  []  275.17 221.32 90 top
NOREF#527  -  []  136.26 263.76 90 top
NOREF#528  -  []  277.03 238.07 0 top
NOREF#529  -  []  83.04 144.22 90 top
NOREF#530  -  []  159.72 219.22 90 top
NOREF#531  -  []  234.39 226.59 90 top
NOREF#532  -  []  276.33 227.9 90 top
NOREF#533  -  []  199.4 210.55 90 top
NOREF#534  -  []  230.56 197.6 0 top
NOREF#535  -  []  235.17 281.32 0 top
NOREF#536  -  []  224.04 191.93 0 top
NOREF#537  -  []  275.17 281.32 0 top
NOREF#538  -  []  93.68 136.27 0 top
NOREF#539  -  []  245.04 233.3 90 top
NOREF#540  -  []  233.94 191.93 0 top
NOREF#541  -  []  251.21 234.24 90 top
NOREF#542  -  []  248.42 268.62 0 top
NOREF#543  -  []  272.25 272.17 90 top
NOREF#544  -  []  183.49 257.85 90 top
NOREF#545  -  []  239.4 264.45 90 top
NOREF#546  -  []  230.97 250.88 90 top
NOREF#547  -  []  225.09 197.49 90 top
NOREF#548  -  []  223.36 187.38 0 top
NOREF#549  -  []  135.02 208.14 90 top
NOREF#550  -  []  131.05 292.28 90 top
NOREF#551  -  []  243.97 213.09 90 top
NOREF#552  -  []  259.73 238.35 0 top
NOREF#553  -  []  154.07 196.43 90 top
NOREF#554  -  []  157.37 196.43 90 top
NOREF#555  -  []  179.08 261.22 0 top
NOREF#556  -  []  188.32 182.05 0 top
NOREF#557  -  []  146.7 237.02 90 top
NOREF#558  -  []  272.25 272.17 0 top
NOREF#559  -  []  136.55 254.49 90 top
NOREF#560  -  []  199.4 202.09 0 top
NOREF#561  -  []  146.88 289.79 0 top
NOREF#562  -  []  167.74 456.29 0 top
NOREF#563  -  []  191.87 456.29 90 top
NOREF#564  -  []  123.92 289.94 0 top
NOREF#565  -  []  237.37 191.6 90 top
NOREF#566  -  []  271.19 283.92 0 top
NOREF#567  -  []  242.2 238.35 0 top
NOREF#568  -  []  157.71 233.69 90 top
NOREF#569  -  []  149.84 213.7 0 top
NOREF#570  -  []  243.97 202.09 0 top
NOREF#571  -  []  199.72 274.65 90 top
NOREF#572  -  []  199.22 179.57 90 top
NOREF#573  -  []  272.63 173.69 0 top
NOREF#574  -  []  288.42 208.62 0 top
NOREF#575  -  []  199.4 274.54 0 top
NOREF#576  -  []  289.52 210.32 90 top
NOREF#577  -  []  232.25 218.02 0 top
NOREF#578  -  []  275.58 202.67 90 top
NOREF#579  -  []  271.79 251.93 0 top
NOREF#580  -  []  150.77 273.37 90 top
NOREF#581  -  []  218.85 181.15 90 top
NOREF#582  -  []  278.64 233.37 90 top
NOREF#583  -  []  178.85 241.15 90 top
NOREF#584  -  []  267.77 181.47 0 top
NOREF#585  -  []  147.3 280.35 0 top
NOREF#586  -  []  153.98 178.07 0 top
NOREF#587  -  []  153.03 172.1 0 top
NOREF#588  -  []  229.84 219.54 90 top
NOREF#589  -  []  192.25 218.02 0 top
NOREF#590  -  []  215.11 261.22 90 top
NOREF#591  -  []  279.27 261.77 0 top
NOREF#592  -  []  228.78 282.65 0 top
NOREF#593  -  []  286.32 212.22 0 top
NOREF#594  -  []  233.18 277.69 90 top
NOREF#595  -  []  268.99 196.75 0 top
NOREF#596  -  []  248.42 267.82 90 top
NOREF#597  -  []  233.39 253.03 90 top
NOREF#598  -  []  196.02 241.47 0 top
NOREF#599  -  []  179.55 234.49 0 top
NOREF#600  -  []  271.95 238.07 0 top
NOREF#601  -  []  186.43 222.5 90 top
NOREF#602  -  []  185.42 214.72 90 top
NOREF#603  -  []  146.96 196.43 90 top
NOREF#604  -  []  166.32 272.22 0 top
NOREF#605  -  []  138.95 206.12 0 top
NOREF#606  -  []  222.87 226.99 0 top
NOREF#607  -  []  150.98 244.35 0 top
NOREF#608  -  []  199.27 260.97 90 top
NOREF#609  -  []  276.57 245.63 90 top
NOREF#610  -  []  175.84 202.57 90 top
NOREF#611  -  []  169.52 207.27 90 top
NOREF#612  -  []  279.27 265.58 0 top
NOREF#613  -  []  118.64 291.4 90 top
NOREF#614  -  []  243.4 236.38 0 top
NOREF#615  -  []  129.44 260.67 90 top
NOREF#616  -  []  163.97 213.09 90 top
NOREF#617  -  []  256.26 263.76 90 top
NOREF#618  -  []  216.63 232.23 0 top
NOREF#619  -  []  167.95 286.12 90 top
NOREF#620  -  []  190.98 244.35 0 top
NOREF#621  -  []  168.45 295.2 0 top
NOREF#622  -  []  227.43 278.27 90 top
NOREF#623  -  []  149.29 276.17 90 top
NOREF#624  -  []  279.4 270.55 90 top
NOREF#625  -  []  210.89 202.32 0 top
NOREF#626  -  []  230.48 175.77 0 top
NOREF#627  -  []  150.77 223.79 90 top
NOREF#628  -  []  146.83 251.93 0 top
NOREF#629  -  []  232.72 252.78 0 top
NOREF#630  -  []  193.6 282.39 0 top
NOREF#631  -  []  299.62 18.69 90 top
NOREF#632  -  []  218.95 261.55 0 top
NOREF#633  -  []  260.83 201.22 90 top
NOREF#634  -  []  215.24 261.55 90 top
NOREF#635  -  []  271.91 256.43 90 top
NOREF#636  -  []  276.81 172.54 0 top
NOREF#637  -  []  191.79 251.93 0 top
NOREF#638  -  []  231.19 288.49 0 top
NOREF#639  -  []  273.27 253.35 0 top
NOREF#640  -  []  263.89 185.24 90 top
NOREF#641  -  []  233.39 257.85 90 top
NOREF#642  -  []  169.49 220.89 0 top
NOREF#643  -  []  233.83 172.21 90 top
NOREF#644  -  []  183.49 197.85 90 top
NOREF#645  -  []  133.68 389.27 90 top
NOREF#646  -  []  218.35 267.01 0 top
NOREF#647  -  []  159.27 273.41 90 top
NOREF#648  -  []  157.25 180.62 0 top
NOREF#649  -  []  232.13 280.09 0 top
NOREF#650  -  []  208.54 265.9 0 top
NOREF#651  -  []  288.54 267.5 90 top
NOREF#652  -  []  151.91 251.6 90 top
NOREF#653  -  []  258.35 211.84 0 top
NOREF#654  -  []  193.95 251.93 0 top
NOREF#655  -  []  143.36 258.18 0 top
NOREF#656  -  []  155.17 216.75 0 top
NOREF#657  -  []  228.32 253.35 0 top
NOREF#658  -  []  248.42 265.58 0 top
NOREF#659  -  []  279.65 272.56 0 top
NOREF#660  -  []  127.95 226.12 90 top
NOREF#661  -  []  152.25 222.59 90 top
NOREF#662  -  []  144.16 245.63 90 top
NOREF#663  -  []  258.95 206.12 0 top
NOREF#664  -  []  197.37 180.3 90 top
NOREF#665  -  []  241.75 214.76 0 top
NOREF#666  -  []  190.98 184.35 0 top
NOREF#667  -  []  131.26 244.35 0 top
NOREF#668  -  []  168.42 260.97 90 top
NOREF#669  -  []  289.52 200.42 90 top
NOREF#670  -  []  271.24 193.03 90 top
NOREF#671  -  []  159.4 267.5 90 top
NOREF#672  -  []  276.61 173.37 90 top
NOREF#673  -  []  204.61 294.24 90 top
NOREF#674  -  []  275.05 278.82 0 top
NOREF#675  -  []  171.22 294.89 90 top
NOREF#676  -  []  189.72 221.62 0 top
NOREF#677  -  []  143.36 193.35 0 top
NOREF#678  -  []  269.84 279.54 90 top
NOREF#679  -  []  143.89 185.24 90 top
NOREF#680  -  []  284.95 210.32 90 top
NOREF#681  -  []  95.35 396.29 0 top
NOREF#682  -  []  290.89 262.32 0 top
NOREF#683  -  []  213.36 261.22 0 top
NOREF#684  -  []  171.25 184.35 0 top
NOREF#685  -  []  279.27 273.41 90 top
NOREF#686  -  []  276.54 227 0 top
NOREF#687  -  []  283.97 262.09 0 top
NOREF#688  -  []  249.52 210.32 90 top
NOREF#689  -  []  141.43 285.38 90 top
NOREF#690  -  []  178.95 266.12 0 top
NOREF#691  -  []  221.59 308.11 0 top
NOREF#692  -  []  163.97 268.95 0 top
NOREF#693  -  []  279.27 267.82 90 top
NOREF#694  -  []  153.18 244.35 0 top
NOREF#695  -  []  201.84 295.2 0 top
NOREF#696  -  []  237.04 184.35 0 top
NOREF#697  -  []  147.99 178.35 0 top
NOREF#698  -  []  168.42 201.77 0 top
NOREF#699  -  []  219.73 178.35 0 top
NOREF#700  -  []  193.56 233.37 90 top
NOREF#701  -  []  270.6 173.69 0 top
NOREF#702  -  []  272.66 166.36 90 top
NOREF#703  -  []  249.52 207.27 90 top
NOREF#704  -  []  243.84 201.77 0 top
NOREF#705  -  []  197.04 244.35 0 top
NOREF#706  -  []  148.99 251.93 0 top
NOREF#707  -  []  201.12 188.11 90 top
NOREF#708  -  []  158.91 232.21 90 top
NOREF#709  -  []  267.43 284.11 90 top
NOREF#710  -  []  166.32 262.32 0 top
NOREF#711  -  []  294.09 260.42 90 top
NOREF#712  -  []  229.24 185.31 90 top
NOREF#713  -  []  204.95 270.32 90 top
NOREF#714  -  []  157.92 247.68 90 top
NOREF#715  -  []  154.63 283.79 90 top
NOREF#716  -  []  249.17 231.95 0 top
NOREF#717  -  []  152.13 284.66 0 top
NOREF#718  -  []  152.66 166.36 90 top
NOREF#719  -  []  188.99 196.75 0 top
NOREF#720  -  []  201.75 209.17 0 top
NOREF#721  -  []  193.27 258.18 0 top
NOREF#722  -  []  116.51 14.59 90 top
NOREF#723  -  []  272.63 233.69 0 top
NOREF#724  -  []  164.95 212.86 90 top
NOREF#725  -  []  150.15 206.89 90 top
NOREF#726  -  []  240.11 18.69 0 top
NOREF#727  -  []  283.97 210.55 90 top
NOREF#728  -  []  150.56 197.6 0 top
NOREF#729  -  []  163.97 273.09 90 top
NOREF#730  -  []  170.02 274.45 0 top
NOREF#731  -  []  181.94 389.27 90 top
NOREF#732  -  []  156.54 227 0 top
NOREF#733  -  []  159.4 202.09 0 top
NOREF#734  -  []  230.77 219.22 90 top
NOREF#735  -  []  276.52 216.55 0 top
NOREF#736  -  []  134.38 204.09 0 top
NOREF#737  -  []  242.44 292.28 0 top
NOREF#738  -  []  152.72 192.78 0 top
NOREF#739  -  []  236.7 241.72 90 top
NOREF#740  -  []  237.18 176.17 90 top
NOREF#741  -  []  229.72 275.77 0 top
NOREF#742  -  []  210.92 291.95 90 top
NOREF#743  -  []  225 456.29 0 top
NOREF#744  -  []  159.72 223.79 90 top
NOREF#745  -  []  195.68 173.69 90 top
NOREF#746  -  []  236.1 276.42 90 top
NOREF#747  -  []  223.49 247.06 90 top
NOREF#748  -  []  88.44 106.3 90 top
NOREF#749  -  []  229.72 226.19 0 top
NOREF#750  -  []  283.84 267.82 90 top
NOREF#751  -  []  283.97 202.09 0 top
NOREF#752  -  []  191.53 233.37 90 top
NOREF#753  -  []  236.33 227.9 90 top
NOREF#754  -  []  203.97 204.45 90 top
NOREF#755  -  []  151.73 172.54 0 top
NOREF#756  -  []  232.87 188.11 90 top
NOREF#757  -  []  260.95 264.09 90 top
NOREF#758  -  []  236.81 172.54 0 top
NOREF#759  -  []  270.88 228.6 90 top
NOREF#760  -  []  204.95 264.23 90 top
NOREF#761  -  []  272.63 172.86 0 top
NOREF#762  -  []  179.72 213.6 90 top
NOREF#763  -  []  195.15 176.17 90 top
NOREF#764  -  []  283.04 236.5 90 top
NOREF#765  -  []  236.38 241.15 90 top
NOREF#766  -  []  209.55 237.49 90 top
NOREF#767  -  []  279.4 213.09 90 top
NOREF#768  -  []  221.03 267.69 90 top
NOREF#769  -  []  229.84 219.54 0 top
NOREF#770  -  []  155.49 168.7 90 top
NOREF#771  -  []  288.42 267.82 90 top
NOREF#772  -  []  197.5 245.31 90 top
NOREF#773  -  []  234.39 276.17 90 top
NOREF#774  -  []  155.17 221.32 90 top
NOREF#775  -  []  149.55 188.99 90 top
NOREF#776  -  []  173.24 201.55 0 top
NOREF#777  -  []  267.43 224.11 90 top
NOREF#778  -  []  228.99 251.93 0 top
NOREF#779  -  []  209.55 237.49 90 top
NOREF#780  -  []  172.87 227.4 90 top
NOREF#781  -  []  192.13 284.66 0 top
NOREF#782  -  []  267.9 205.84 90 top
NOREF#783  -  []  220.59 184.98 90 top
NOREF#784  -  []  253.24 201.55 0 top
NOREF#785  -  []  244.95 212.86 90 top
NOREF#786  -  []  161.84 295.2 0 top
NOREF#787  -  []  183.36 253.35 0 top
NOREF#788  -  []  179.73 238.35 0 top
NOREF#789  -  []  312.52 456.29 90 top
NOREF#790  -  []  239.27 274.21 0 top
NOREF#791  -  []  209.52 212.86 90 top
NOREF#792  -  []  187.9 265.84 90 top
NOREF#793  -  []  202.2 178.35 0 top
NOREF#794  -  []  283.84 207.82 90 top
NOREF#795  -  []  142.88 273.02 0 top
NOREF#796  -  []  186.7 297.01 90 top
NOREF#797  -  []  281.44 184.35 0 top
NOREF#798  -  []  223.36 258.18 0 top
NOREF#799  -  []  196.52 281.12 0 top
NOREF#800  -  []  190.6 233.69 90 top
NOREF#801  -  []  199.06 178.07 0 top
NOREF#802  -  []  159.27 271.67 0 top
NOREF#803  -  []  183.89 245.24 90 top
NOREF#804  -  []  196.7 193.03 90 top
NOREF#805  -  []  208.54 264.45 90 top
NOREF#806  -  []  189.55 188.99 90 top
NOREF#807  -  []  273.18 282.26 90 top
NOREF#808  -  []  223.49 197.85 90 top
NOREF#809  -  []  149.12 196.43 90 top
NOREF#810  -  []  151.53 173.37 90 top
NOREF#811  -  []  186.96 256.43 90 top
NOREF#812  -  []  191.18 179.15 0 top
NOREF#813  -  []  203.97 214.54 0 top
NOREF#814  -  []  275.49 18.69 90 top
NOREF#815  -  []  236.02 192.78 0 top
NOREF#816  -  []  233.03 172.1 0 top
NOREF#817  -  []  188.35 277.95 90 top
NOREF#818  -  []  162.44 232.28 0 top
NOREF#819  -  []  226.16 272.17 90 top
NOREF#820  -  []  275.96 168.6 90 top
NOREF#821  -  []  212.55 250.49 90 top
NOREF#822  -  []  277.71 173.69 0 top
NOREF#823  -  []  248.42 205.58 0 top
NOREF#824  -  []  201.75 212.22 0 top
NOREF#825  -  []  146.96 251.6 90 top
NOREF#826  -  []  202.44 292.28 0 top
NOREF#827  -  []  270.98 244.35 0 top
NOREF#828  -  []  277.03 178.07 0 top
NOREF#829  -  []  286.32 274.76 0 top
NOREF#830  -  []  161.75 274.76 0 top
NOREF#831  -  []  233.18 244.35 0 top
NOREF#832  -  []  156.57 193.35 0 top
NOREF#833  -  []  164.44 232.28 90 top
NOREF#834  -  []  154.07 256.43 90 top
NOREF#835  -  []  270.77 279.22 90 top
NOREF#836  -  []  258.95 266.12 0 top
NOREF#837  -  []  174.04 210.63 90 top
NOREF#838  -  []  158.11 232.1 0 top
NOREF#839  -  []  270.97 239.57 90 top
NOREF#840  -  []  267.45 209.24 0 top
NOREF#841  -  []  196.84 167.33 0 top
NOREF#842  -  []  147.8 265.39 90 top
NOREF#843  -  []  203.97 210.55 90 top
NOREF#844  -  []  93.68 156.59 0 top
NOREF#845  -  []  272.25 278.02 90 top
NOREF#846  -  []  197.5 185.31 90 top
NOREF#847  -  []  192.87 248.11 90 top
NOREF#848  -  []  226.01 244.91 90 top
NOREF#849  -  []  156.02 252.5 0 top
NOREF#850  -  []  227.05 269.24 0 top
NOREF#851  -  []  240.13 456.29 90 top
NOREF#852  -  []  213.45 244.35 0 top
NOREF#853  -  []  157.25 196.75 0 top
NOREF#854  -  []  147.9 205.84 90 top
NOREF#855  -  []  209.55 237.49 90 top
NOREF#856  -  []  211.21 294.89 90 top
NOREF#857  -  []  208.45 235.2 0 top
NOREF#858  -  []  248.94 221.73 0 top
NOREF#859  -  []  149.84 219.54 0 top
NOREF#860  -  []  152.13 224.66 0 top
NOREF#861  -  []  270.56 252.78 0 top
NOREF#862  -  []  185.61 197.6 0 top
NOREF#863  -  []  153.95 251.93 0 top
NOREF#864  -  []  254.07 270.89 90 top
NOREF#865  -  []  191.73 232.54 0 top
NOREF#866  -  []  161.41 167.9 90 top
NOREF#867  -  []  225.61 197.6 0 top
NOREF#868  -  []  272.72 252.78 0 top
NOREF#869  -  []  208.42 260.97 90 top
NOREF#870  -  []  203.84 205.58 0 top
NOREF#871  -  []  189.72 226.19 0 top
NOREF#872  -  []  226.01 184.91 90 top
NOREF#873  -  []  159.27 214.21 0 top
NOREF#874  -  []  216.38 204.09 90 top
NOREF#875  -  []  228.32 258.18 0 top
NOREF#876  -  []  226.43 282.49 90 top
NOREF#877  -  []  229.55 248.99 90 top
NOREF#878  -  []  156.33 227.9 90 top
NOREF#879  -  []  163.84 213.41 90 top
NOREF#880  -  []  195.96 228.6 90 top
NOREF#881  -  []  276.1 280.99 90 top
NOREF#882  -  []  267.8 265.39 90 top
NOREF#883  -  []  156.02 181.47 0 top
NOREF#884  -  []  151.11 253.35 0 top
NOREF#885  -  []  236.52 225.69 0 top
NOREF#886  -  []  261.59 248.12 0 top
NOREF#887  -  []  149.56 259.27 90 top
NOREF#888  -  []  193.39 193.03 90 top
NOREF#889  -  []  165.04 233.3 90 top
NOREF#890  -  []  237.25 240.62 0 top
NOREF#891  -  []  157.71 173.69 90 top
NOREF#892  -  []  195.58 202.67 90 top
NOREF#893  -  []  277.5 245.31 90 top
NOREF#894  -  []  198.64 173.37 90 top
NOREF#895  -  []  169.52 267.27 90 top
NOREF#896  -  []  202.2 178.35 0 top
NOREF#897  -  []  279.27 264.78 90 top
NOREF#898  -  []  270.77 283.79 90 top
NOREF#899  -  []  150.6 233.69 0 top
NOREF#900  -  []  231.24 253.03 90 top
NOREF#901  -  []  183.36 247.38 0 top
NOREF#902  -  []  253.78 267.01 0 top
NOREF#903  -  []  153.18 217.69 90 top
NOREF#904  -  []  159.27 268.62 0 top
NOREF#905  -  []  180.83 261.22 90 top
NOREF#906  -  []  226.83 191.93 0 top
NOREF#907  -  []  273.03 172.1 0 top
NOREF#908  -  []  199.4 260.64 90 top
NOREF#909  -  []  222.87 286.99 0 top
NOREF#910  -  []  162.26 176.17 90 top
NOREF#911  -  []  145.42 214.72 90 top
NOREF#912  -  []  276.02 257.6 0 top
NOREF#913  -  []  184.04 256.75 0 top
NOREF#914  -  []  227.8 209.99 0 top
NOREF#915  -  []  267.43 218.27 90 top
NOREF#916  -  []  227.8 265.39 90 top
NOREF#917  -  []  276.7 257.85 90 top
NOREF#918  -  []  229.12 251.6 90 top
NOREF#919  -  []  248.45 235.2 0 top
NOREF#920  -  []  237.03 178.07 0 top
NOREF#921  -  []  191.73 172.54 0 top
NOREF#922  -  []  156.38 241.15 90 top
NOREF#923  -  []  199.22 239.57 90 top
NOREF#924  -  []  221.85 232.5 0 top
NOREF#925  -  []  187.43 278.27 0 top
NOREF#926  -  []  231.91 251.6 90 top
NOREF#927  -  []  263.49 257.85 90 top
NOREF#928  -  []  220.95 266.12 90 top
NOREF#929  -  []  145.09 257.49 90 top
NOREF#930  -  []  154.63 277.85 0 top
NOREF#931  -  []  199.22 250.88 90 top
NOREF#932  -  []  181.03 267.69 90 top
NOREF#933  -  []  209.55 237.49 90 top
NOREF#934  -  []  237.04 184.35 0 top
NOREF#935  -  []  85.59 155.57 90 top
NOREF#936  -  []  194.07 191.6 90 top
NOREF#937  -  []  191.95 238.07 0 top
NOREF#938  -  []  220.83 263.76 90 top
NOREF#939  -  []  197.71 173.69 90 top
NOREF#940  -  []  230.6 173.69 90 top
NOREF#941  -  []  141.55 209.94 90 top
NOREF#942  -  []  228.81 250.88 90 top
NOREF#943  -  []  221.55 269.94 90 top
NOREF#944  -  []  263.49 253.03 90 top
NOREF#945  -  []  239.27 264.78 90 top
NOREF#946  -  []  274.39 222.02 90 top
NOREF#947  -  []  254.43 292.23 0 top
NOREF#948  -  []  162.2 178.35 0 top
NOREF#949  -  []  224.04 196.75 0 top
NOREF#950  -  []  197.71 232.86 0 top
NOREF#951  -  []  163.84 273.41 90 top
NOREF#952  -  []  243.84 214.21 0 top
NOREF#953  -  []  131.05 232.28 90 top
NOREF#954  -  []  153.39 197.85 90 top
NOREF#955  -  []  271.53 173.37 90 top
NOREF#956  -  []  164.95 200.42 90 top
NOREF#957  -  []  243.97 273.09 90 top
NOREF#958  -  []  196.1 280.99 90 top
NOREF#959  -  []  195.92 195.7 90 top
NOREF#960  -  []  209.55 237.49 0 top
NOREF#961  -  []  239.65 272.56 0 top
NOREF#962  -  []  144.16 185.63 90 top
NOREF#963  -  []  153.18 271.85 90 top
NOREF#964  -  []  266.83 256.75 0 top
NOREF#965  -  []  203.97 274.54 0 top
NOREF#966  -  []  192.25 282.59 0 top
NOREF#967  -  []  193.18 184.35 0 top
NOREF#968  -  []  271.11 193.35 0 top
NOREF#969  -  []  148.78 222.65 0 top
NOREF#970  -  []  243.97 274.54 0 top
NOREF#971  -  []  227.8 269.99 0 top
NOREF#972  -  []  237.25 196.75 0 top
NOREF#973  -  []  181.6 234.15 0 top
NOREF#974  -  []  227.45 269.24 0 top
NOREF#975  -  []  149.67 190.01 0 top
NOREF#976  -  []  208.45 295.2 0 top
NOREF#977  -  []  198.91 172.21 90 top
NOREF#978  -  []  233.6 282.39 0 top
NOREF#979  -  []  234.39 222.02 90 top
NOREF#980  -  []  163.97 267.5 90 top
NOREF#981  -  []  270.56 197.6 0 top
NOREF#982  -  []  235.17 272.17 90 top
NOREF#983  -  []  146.17 272.17 90 top
NOREF#984  -  []  146.7 223.05 90 top
NOREF#985  -  []  252.64 204.47 0 top
NOREF#986  -  []  152.25 212.18 0 top
NOREF#987  -  []  141.55 207.14 90 top
NOREF#988  -  []  208.54 262.09 0 top
NOREF#989  -  []  260.95 268.91 90 top
NOREF#990  -  []  297.39 456.29 0 top
NOREF#991  -  []  255.02 208.14 90 top
NOREF#992  -  []  196.38 181.15 90 top
NOREF#993  -  []  258.85 181.15 90 top
NOREF#994  -  []  210.89 269.17 0 top
NOREF#995  -  []  186.28 257.85 90 top
NOREF#996  -  []  230.6 233.69 0 top
NOREF#997  -  []  276.84 167.33 0 top
NOREF#998  -  []  228.99 196.75 0 top
NOREF#999  -  []  195.92 255.7 90 top
NOREF#1000  -  []  276.79 171.3 0 top
NOREF#1001  -  []  156.52 216.55 0 top
NOREF#1002  -  []  254.09 264.23 90 top
NOREF#1003  -  []  140.59 184.98 90 top
NOREF#1004  -  []  211.25 244.35 0 top
NOREF#1005  -  []  273.76 250.88 90 top
NOREF#1006  -  []  178.95 201.55 0 top
NOREF#1007  -  []  138.56 246.51 0 top
NOREF#1008  -  []  258.83 232.23 0 top
NOREF#1009  -  []  216 396.29 0 top
NOREF#1010  -  []  269.84 284.11 90 top
NOREF#1011  -  []  217.25 176.5 90 top
NOREF#1012  -  []  190.77 223.79 90 top
NOREF#1013  -  []  147.05 209.24 0 top
NOREF#1014  -  []  279.72 283.79 90 top
NOREF#1015  -  []  228.78 244.35 0 top
NOREF#1016  -  []  277.37 191.6 90 top
NOREF#1017  -  []  199.27 207.82 90 top
NOREF#1018  -  []  269.84 224.11 0 top
NOREF#1019  -  []  149.67 252.5 90 top
NOREF#1020  -  []  156.57 253.35 0 top
NOREF#1021  -  []  284.95 264.23 90 top
NOREF#1022  -  []  179.08 208.59 0 top
NOREF#1023  -  []  145.61 254.08 0 top
NOREF#1024  -  []  114.62 458.49 0 top
NOREF#1025  -  []  211.21 294.24 90 top
NOREF#1026  -  []  268.99 251.93 0 top
NOREF#1027  -  []  90.48 16.49 0 top
NOREF#1028  -  []  276.1 220.99 90 top
NOREF#1029  -  []  272.72 257.6 0 top
NOREF#1030  -  []  271.19 228.49 0 top
NOREF#1031  -  []  273.76 255.7 90 top
NOREF#1032  -  []  230.97 190.88 90 top
NOREF#1033  -  []  229.12 180.3 90 top
NOREF#1034  -  []  218.95 266.12 0 top
NOREF#1035  -  []  168.94 281.73 0 top
NOREF#1036  -  []  209.55 237.49 0 top
NOREF#1037  -  []  139.08 268.59 0 top
NOREF#1038  -  []  195.58 262.67 90 top
NOREF#1039  -  []  284.95 200.42 90 top
NOREF#1040  -  []  279.06 238.07 0 top
NOREF#1041  -  []  218.35 211.84 0 top
NOREF#1042  -  []  268.81 190.88 90 top
NOREF#1043  -  []  250.89 206.13 0 top
NOREF#1044  -  []  137.25 176.5 90 top
NOREF#1045  -  []  132.55 284.49 0 top
NOREF#1046  -  []  259.73 178.35 0 top
NOREF#1047  -  []  150.88 228.6 90 top
NOREF#1048  -  []  275.17 216.75 0 top
NOREF#1049  -  []  269.84 279.54 0 top
NOREF#1050  -  []  264.04 185.96 0 top
NOREF#1051  -  []  260.59 244.98 90 top
NOREF#1052  -  []  156.8 220.49 90 top
NOREF#1053  -  []  149.72 221.62 0 top
NOREF#1054  -  []  277.04 184.35 0 top
NOREF#1055  -  []  121.84 235.2 0 top
NOREF#1056  -  []  244.32 231.95 90 top
NOREF#1057  -  []  88.14 155.19 0 top
NOREF#1058  -  []  138.95 261.55 0 top
NOREF#1059  -  []  266.96 191.6 90 top
NOREF#1060  -  []  157.71 172.86 0 top
NOREF#1061  -  []  196.8 220.49 90 top
NOREF#1062  -  []  155.56 235.77 0 top
NOREF#1063  -  []  209.52 267.27 90 top
NOREF#1064  -  []  188.32 245.63 0 top
NOREF#1065  -  []  162.57 291.95 0 top
NOREF#1066  -  []  276.81 232.54 0 top
NOREF#1067  -  []  239.24 184.35 0 top
NOREF#1068  -  []  147.43 284.11 90 top
NOREF#1069  -  []  176.55 280.49 0 top
NOREF#1070  -  []  237.03 238.07 0 top
NOREF#1071  -  []  246.32 266.13 0 top
NOREF#1072  -  []  132.26 237.5 0 top
NOREF#1073  -  []  275.51 454.29 90 top
NOREF#1074  -  []  187.9 205.84 90 top
NOREF#1075  -  []  234.33 267.37 90 top
NOREF#1076  -  []  235.17 216.75 0 top
NOREF#1077  -  []  137.28 286.47 0 top
NOREF#1078  -  []  151.79 196.75 0 top
NOREF#1079  -  []  228.78 288.49 0 top
NOREF#1080  -  []  156.02 248.11 90 top
NOREF#1081  -  []  220.59 244.98 90 top
NOREF#1082  -  []  135.15 263.21 0 top
NOREF#1083  -  []  238.64 233.37 90 top
NOREF#1084  -  []  288.42 268.62 0 top
NOREF#1085  -  []  199.27 208.62 0 top
NOREF#1086  -  []  216.63 292.23 0 top
NOREF#1087  -  []  302.59 389.27 90 top
NOREF#1088  -  []  210.89 206.13 0 top
NOREF#1089  -  []  215.11 201.22 90 top
NOREF#1090  -  []  272.13 274.25 0 top
NOREF#1091  -  []  277.25 251.93 0 top
NOREF#1092  -  []  206.32 209.17 0 top
NOREF#1093  -  []  226.83 251.93 0 top
NOREF#1094  -  []  131.26 184.35 0 top
NOREF#1095  -  []  229.84 213.7 90 top
NOREF#1096  -  []  147.05 269.24 0 top
NOREF#1097  -  []  239.4 200.64 90 top
NOREF#1098  -  []  211.21 234.24 90 top
NOREF#1099  -  []  232.11 231.4 0 top
NOREF#1100  -  []  167.98 226.38 90 top
NOREF#1101  -  []  138.95 266.12 0 top
NOREF#1102  -  []  196.57 182.05 0 top
